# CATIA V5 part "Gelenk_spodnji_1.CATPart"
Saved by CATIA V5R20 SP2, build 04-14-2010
Part number: Gelenk_spodnji_1
Bounding box of the stored display mesh (mm): x -4.8 to 4.8, y 0 to 25, z -29.795 to 29.795
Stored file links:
  C:\Documents and Settings\Administrator\My Documents\Hobi_dokumenti\CAD_CNC\Clap_CATIA\Gelenk_spodnji_1.CATPart
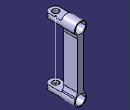
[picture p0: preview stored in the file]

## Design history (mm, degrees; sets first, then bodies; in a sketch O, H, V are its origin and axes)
Set1
  Point1: type Center, Curve edge [face of Pocket1 from Sketch2.L5 | face of Pocket2 from Sketch3.A1]
  Point2: type Center, Curve edge [face of Mirror1 | face of Mirror1]
  Line1: type PtPt, FirstPoint Point2, SecondPoint Point1
Body1 (main body)
  Sketch1 on xy-plane, origin (0, 0, 0), H (1, 0, 0), V (0, 1, 0)
    line L1 (0, 0) -> (-4.8, 0)
    line L2 (-4.8, 0) -> (-4.8, 25)
    line L3 (-4.8, 25) -> (0, 25)
    line L4 (0, 25) -> (0, 0)
    point P1 (-4.8, 0)
    point P3 (0, 25)
    distance O P1 = 4.8
    distance P3 O = 25
    horizontal: L1 H, L3 H
    vertical: L2 V, L4 V
    perpendicularity: L1 L2
  Shaft1: profile Sketch1, axis Sketch1.L4, angle 360
  Translate1: ToTransfor Shaft1, Direction xy-plane, Length 25
  Sketch2 on yz-plane, origin (0, 0, 0), H (0, 1, 0), V (0, 0, 1)
    line L1 (-3.9957, 30.9) -> (14, 30.9)
    line L2 (14, 30.9) -> (14, 26.9)
    line L3 (14, 26.9) -> (-3.9957, 26.9)
    line L4 (-3.9957, 26.9) -> (-3.9957, 30.9)
    point P5 (-3.9957, 23.1)
    line L5 (-3.9957, 23.1) -> (14, 23.1)
    line L6 (14, 23.1) -> (14, 19.1)
    line L7 (14, 19.1) -> (-3.9957, 19.1)
    line L8 (-3.9957, 19.1) -> (-3.9957, 23.1)
    point P7 (14, 19.1)
    reference projected line E1 through (0, 25) direction (1, 0) from axis of face of Shaft1 from Sketch1.L2
    reference projected line E2 through (0, 25) direction (1, 0) from axis of face of Shaft1 from Sketch1.L2
    reference projected line E3 (0, 29.8) -> (0, 20.2) from edge [face of Shaft1 from Sketch1.L1 | face of Shaft1 from Sketch1.L2]
    distance E1 L5 = 1.9
    distance E2 L3 = 1.9
    distance E3 L2 = 14
    length L8 = 4
    length L4 = 4
    horizontal: L1 H, L3 H, L5 H, L7 H
    vertical: L2 V, L4 V, L6 V, L8 V
    coincidence: P5 L4, P7 L2
  Pocket1: profile Sketch2, direction (1, 0, 0), length 20, mirrored extent
  Sketch3 on xy-plane, origin (0, 0, 0), H (1, 0, 0), V (0, 1, 0)
    circle A1 centre (0, 4.9462) radius 2.5
    point P1 (0, 4.9462)
    arc A2 centre (0, 4.9462) radius 5 from (-5, 4.9462) to (5, 4.9462) ccw
    line L1 (8.2326, 4.9462) -> (5, 4.9462)
    line L2 (-8.288, 4.9462) -> (-8.288, -1.7558)
    line L3 (-8.288, -1.7558) -> (8.2326, -1.7558)
    line L4 (8.2326, -1.7558) -> (8.2326, 4.9462)
    point P6 (-5, 4.9462)
    line L5 (-5, 4.9462) -> (-8.288, 4.9462)
    radius A1 = 2.5
    radius A2 = 5
    coincidence: P1 V, L1 P6
    horizontal: L1 H, L3 H, L5 H
    vertical: L2 V, L4 V
  Pocket2: profile Sketch3, direction (0, 0, 1), through (limit type 6)
  Mirror1: of the body so far, about xy-plane
  Sketch4 on face of Shaft1 from Sketch1.L3, origin (0, 25, 0), H (-1, 0, 0), V (0, 0, 1)
    line L1 (-2.5, 25) -> (2.5, 25)
    line L2 (2.5, 25) -> (2.5, -25)
    line L3 (2.5, -25) -> (-2.5, -25)
    line L4 (-2.5, -25) -> (-2.5, 25)
    distance V L2 = 2.5
    length L4 = 50
    distance H L3 = 25
    distance V L4 = 2.5
    horizontal: L1 H, L3 H
    vertical: L2 V, L4 V
  Pad1: profile Sketch4, direction (0, -1, 0), up to face of Pocket1 from Sketch2.L6
  Fillet1: radius 5, on edge [face of Shaft1 from Sketch1.L2 | face of Pad1 from Sketch4.L4]; edge [face of Pad1 from Sketch4.L2 | face of Shaft1 from Sketch1.L2]; edge [face of Pad1 from Sketch4.L4 | face of Mirror1]; edge [face of Mirror1 | face of Pad1 from Sketch4.L2]
  Sketch5 on face of Mirror1, origin (0, 25, 0), H (-1, 0, 0), V (0, 0, 1)
    circle A1 centre (0, 25) radius 4
    point P1 (0, 25)
    circle A2 centre (0, -25) radius 4
    point P2 (0, -25)
    reference intersected line E1 through (0, 0) direction (-1, 0) from xy-plane
    reference intersected line E2 through (0, 0) direction (0, -1) from yz-plane
    radius A1 = 4
    radius A2 = 4
    distance P2 H = 25
    distance P1 H = 25
    coincidence: P1 V, P2 V, E2 P1
    vertical: E2 V
    horizontal: E1 H
  Pocket3: profile Sketch5, direction (0, -1, 0), length 10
